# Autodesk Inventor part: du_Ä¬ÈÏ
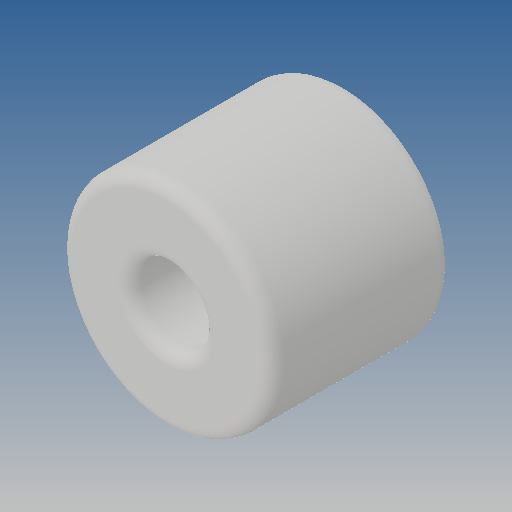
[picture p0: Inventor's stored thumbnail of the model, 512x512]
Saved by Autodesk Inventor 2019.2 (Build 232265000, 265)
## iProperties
Created: 2011-12
Part Number: du_Ä¬ÈÏ
Material: Ogólny
Document SubType Name: Modeling
Designer: CADENGINEERING4
Density: 1 g/cm^3
Appearance: Domyślna
Author: CADENGINEERING4
Revision Number: ÈÎºÎ
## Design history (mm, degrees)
feature "NONE"
node "Bryła1"
